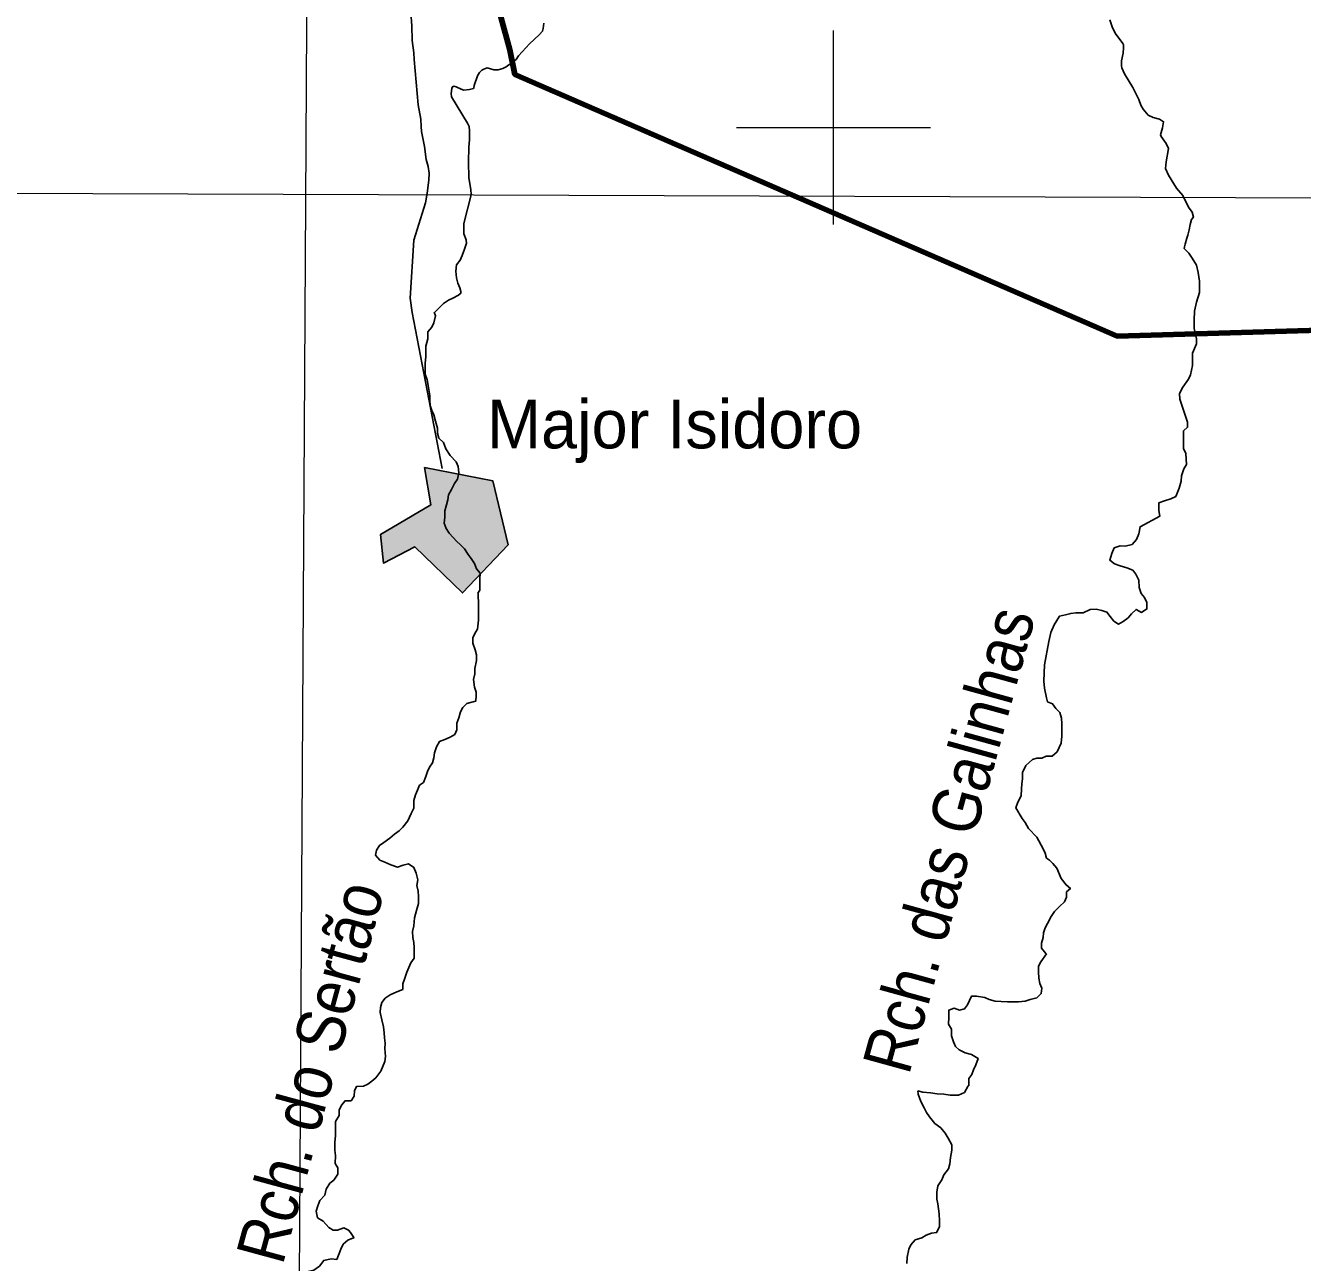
# Model space of a CAD drawing. Extents: x 553962 to 842807, y 8883888 to 9032388.
# Drawn here: x 716676 to 729831, y 8938306 to 8951050 of the extents above; entities that cross this region are included whole.
import ezdxf
from ezdxf.enums import TextEntityAlignment as Align

# ---------------------------------------------------------------- set-up
doc = ezdxf.new("R2010")
doc.units = 0
doc.header["$LTSCALE"] = 200
for name, color, linetype, lineweight in [('1', 7, 'Continuous', 13), ('12', 7, 'Continuous', 25), ('2', 7, 'Continuous', 13), ('21', 7, 'Continuous', 25), ('24', 7, 'Continuous', 25), ('9', 7, 'Continuous', 90)]:
    doc.layers.add(name, color=color, linetype=linetype, lineweight=lineweight)
doc.layers.add('41', color=7, linetype='Continuous')
doc.layers.add('49', color=7, linetype='Continuous')

msp = doc.modelspace()

# ---------------------------------------------------------------- hatches: boundary and pattern name
at = {"layer": '21'}
msp.add_hatch(color=256, dxfattribs=at).paths.add_polyline_path([(720787.1, 8946496.4), (720850.6, 8946110.2), (720334.5, 8945806.5), (720363, 8945511.1), (720684.9, 8945680.2), (721175.9, 8945203.6), (721647.6, 8945700.8), (721491.5, 8946358.8)])

# ---------------------------------------------------------------- linework, layer by layer
at = {"layer": '1'}
msp.add_line((565315.3, 8949866.8), (791497.7, 8949052.2), dxfattribs=at)
msp.add_lwpolyline([(719978.9, 9023574.5), (719561.6, 8949232.2), (719215.6, 8890710.6)], dxfattribs=at)
at = {"layer": '12'}
for points in [[(720644.9, 8951350), (720646.6, 8951317.5), (720645, 8951184.2), (720655.2, 8951046.6), (720660.7, 8950896.5), (720676.6, 8950767.3), (720679.5, 8950698.6), (720720, 8950234.3), (720748.8, 8950083.7), (720750.6, 8950010.8), (720756.6, 8949959.2), (720786.4, 8949804.4), (720801.7, 8949671.1), (720822.7, 8949598), (720833.3, 8949529.3), (720830.9, 8949456.4), (720814.3, 8949323), (720797.8, 8949224.2)], [(720797.8, 8949224.2), (720675.5, 8948838), (720637.7, 8948242.1), (720657.5, 8948094.3), (720969.8, 8946485.6)]]:
    msp.add_lwpolyline(points, dxfattribs=at)
at = {"layer": '2'}
for p, q in [((725000, 8949000), (725000, 8951000)), ((724000, 8950000), (726000, 8950000))]:
    msp.add_line(p, q, dxfattribs=at)
at = {"layer": '21'}
msp.add_lwpolyline([(720787.1, 8946496.4), (720850.6, 8946110.2), (720334.5, 8945806.5), (720363, 8945511.1), (720684.9, 8945680.2), (721175.9, 8945203.6), (721647.6, 8945700.8), (721491.5, 8946358.8)], close=True, dxfattribs=at)
at = {"layer": '24'}
for points in [[(722016.1, 8951074.9), (722008, 8951019.3), (722000.1, 8950992.6), (721969, 8950952.7), (721869.3, 8950860.9), (721753, 8950739.2), (721728.9, 8950700.5), (721627.2, 8950625.8), (721594.7, 8950607.3), (721543.8, 8950594), (721500.2, 8950594.2), (721433.2, 8950614.3), (721396.2, 8950601.1), (721377.1, 8950590.3), (721351, 8950564.9), (721332.8, 8950532.1), (721297.2, 8950432.1), (721294.4, 8950408.3), (721289.9, 8950402.2), (721248.6, 8950389.7), (721192.8, 8950385.5), (721162.4, 8950393.5), (721112.3, 8950419.6), (721087.2, 8950423.9), (721075.9, 8950419.2), (721066.9, 8950399.9), (721059.7, 8950351.2), (721065.8, 8950315.3), (721229.4, 8950044.8), (721245.2, 8950008.3), (721250.1, 8949966.3)], [(727845.7, 8951109.5), (727868.8, 8951037.2), (727900.2, 8950972.9), (727980.7, 8950863.7), (727986.6, 8950849.9), (727988.4, 8950820.9), (727984.7, 8950765.2), (727967.7, 8950684.6), (727966.2, 8950633.4), (727970.7, 8950612.8), (727995.9, 8950553.3), (728084, 8950413), (728146, 8950288.8), (728166.5, 8950228.6), (728190.4, 8950188.3), (728241.6, 8950126.4), (728291.3, 8950100.9), (728357.7, 8950086.8), (728400.8, 8950059.1), (728388.3, 8949995.5), (728368.3, 8949923.4), (728374.6, 8949907.3), (728428.1, 8949834.8), (728450.3, 8949782.8), (728425.1, 8949647.1), (728421, 8949575.3), (728450.8, 8949507.4), (728532.8, 8949374.5), (728598.3, 8949300.4), (728656.5, 8949177.3)], [(721250.1, 8949966.3), (721250.2, 8949871.2), (721250.2, 8949871.2), (721243.6, 8949796.7), (721237.8, 8949646.3), (721241.5, 8949480.6), (721262.5, 8949362.2), (721267.9, 8949307.1), (721191.4, 8949010.2)], [(728656.5, 8949177.3), (728694.1, 8949128.8), (728707.6, 8949076.1), (728689.3, 8949050.9), (728673.1, 8949000.2), (728664.5, 8948946.7), (728650.8, 8948890.9), (728640, 8948857.9), (728623.6, 8948797), (728615.5, 8948769.1), (728612.7, 8948751.6)], [(721191.4, 8949010.2), (721191, 8948954.2), (721190.6, 8948903.3), (721215.6, 8948842), (721218.6, 8948805.4)], [(721219.8, 8948809.2), (721199.7, 8948745.4), (721173.8, 8948679.3), (721153.2, 8948633.6), (721114.3, 8948584.8), (721107.6, 8948519.8), (721114.3, 8948450.3), (721131.2, 8948394.4), (721151.2, 8948348.5), (721164.9, 8948297.2)], [(728612.7, 8948751.6), (728660.2, 8948703.4), (728695.4, 8948652.3), (728740.7, 8948580.7), (728755.4, 8948504.2), (728770.1, 8948417.6), (728769.8, 8948366.6), (728769.3, 8948300.4), (728738.1, 8948198.8), (728717.1, 8948107.2), (728716.5, 8948015.6), (728715.9, 8947929), (728740.6, 8947821.9), (728740.2, 8947771), (728698.8, 8947674.5), (728698.3, 8947603.2), (728698, 8947547.2), (728677, 8947450.6), (728656.3, 8947404.9), (728599.8, 8947323.7), (728563.7, 8947257.7), (728568.4, 8947201.7), (728648.1, 8946961.9), (728647.8, 8946910.9), (728606.8, 8946875.6), (728606.5, 8946824.6), (728605.9, 8946743.2), (728605.6, 8946692.2), (728630.7, 8946641.2), (728635, 8946529.1), (728609.2, 8946483.4), (728583.3, 8946412.3), (728582.9, 8946356.3), (728562.1, 8946285.1), (728525.9, 8946198.8), (728474.8, 8946173.6), (728408.6, 8946153.6), (728352.5, 8946133.6), (728351.9, 8946052.1), (728361.7, 8945996.1), (728366, 8945992.5)], [(721162.8, 8948295.4), (721135.4, 8948272.2), (721079.2, 8948242), (721033.3, 8948221.9), (720982.2, 8948186.6), (720946.4, 8948151.1), (720887.8, 8948093.3)], [(720886.8, 8948096.7), (720898.2, 8948057.6), (720882.5, 8947986.4), (720861.8, 8947940.7), (720820.8, 8947895.1), (720820.3, 8947823.8), (720799.5, 8947747.6), (720798.7, 8947640.7), (720793.1, 8947569.4), (720792.8, 8947518.5), (720792.4, 8947457.4), (720812.3, 8947401.2), (720827, 8947319.7), (720841.7, 8947238.1), (720841.4, 8947187.2), (720846.1, 8947136.2), (720861, 8947085.2), (720881, 8947039.2), (720900.9, 8946972.9), (720920.8, 8946901.5), (720920.4, 8946850.6), (720935.3, 8946799.6), (720980.8, 8946753.5), (721005.7, 8946687.1), (721051.1, 8946620.6), (721111.6, 8946554.1), (721131.6, 8946508.1), (721141.3, 8946441.8), (721125.6, 8946375.7), (721094.8, 8946330.1), (721063.9, 8946269.2), (721033, 8946213.3), (721027.5, 8946162.4), (721011.9, 8946111.6), (720996.2, 8946050.6), (720995.8, 8945984.4), (720990.3, 8945923.3), (721010.2, 8945867.2), (721040.4, 8945821.2), (721080.8, 8945775.1), (721116.2, 8945739.2), (721156.6, 8945698.2), (721197, 8945657.3), (721237.2, 8945601), (721267.5, 8945560.1)], [(728361.7, 8945996.1), (728157.5, 8945885.3), (728146.8, 8945814.1), (728121, 8945753.1), (728074.9, 8945702.5), (728003.6, 8945687.6), (727952.7, 8945687.9), (727891.5, 8945667.9), (727865.7, 8945612.1), (727844.9, 8945540.9), (727895.5, 8945505), (727951.3, 8945484.2), (728022.4, 8945463.4), (728083.2, 8945437.6), (728113.5, 8945396.7), (728143.5, 8945335.4), (728148.1, 8945259), (728168, 8945197.7), (728203.3, 8945156.8), (728228.4, 8945105.7), (728228, 8945039.5), (728171.8, 8945004.2), (728116, 8945035.1), (728069.9, 8944989.6), (728034.1, 8944949), (727982.9, 8944908.6), (727937, 8944883.4), (727886.3, 8944914.3), (727851, 8944960.3), (727815.8, 8945006.4), (727765, 8945022), (727704.1, 8945037.6), (727643, 8945032.9), (727571.6, 8944997.7), (727495.3, 8944998.2), (727444.4, 8944993.4), (727388.3, 8944978.4), (727327.2, 8944963.6), (727273, 8944875.7), (727239.5, 8944797.4), (727239.5, 8944797.4), (727217.1, 8944704.3), (727172.4, 8944462.1)], [(721267.5, 8945560.1), (721302.7, 8945508.9), (721322.7, 8945452.8), (721358, 8945406.8), (721357.6, 8945345.6), (721357.2, 8945289.6), (721356.8, 8945233.6), (721336.6, 8945202.4)], [(721333.1, 8944831.8), (721314, 8944802.2), (721283.1, 8944746.3), (721282.7, 8944685.2), (721307.7, 8944618.9), (721322.6, 8944567.9), (721322.1, 8944506.8), (721306.3, 8944425.4), (721305.9, 8944369.4), (721290.3, 8944313.4), (721299.9, 8944231.9), (721319.9, 8944180.8), (721319.5, 8944129.9), (721309.9, 8944083.2)], [(727172.4, 8944462.1), (727164.9, 8944294.4), (727172.4, 8944223.6), (727194.7, 8944123), (727205.5, 8944081.4), (727256.2, 8944060.7), (727291.5, 8944014.6), (727331.9, 8943973.7), (727346.8, 8943912.4), (727351.5, 8943856.4), (727351.1, 8943800.4), (727350.6, 8943729.1), (727345, 8943657.8), (727324.3, 8943612.1), (727303.7, 8943566.4), (727252.5, 8943520.9), (727191.5, 8943521.3), (727145.6, 8943501.2), (727094.7, 8943501.5), (727048.8, 8943486.5), (726982.3, 8943425.8), (726946.2, 8943354.7), (726945.7, 8943288.5), (726940.3, 8943237.7), (726934.9, 8943186.8), (726934.4, 8943115.5), (726898.3, 8943049.5), (726877.6, 8942988.5), (726942.9, 8942881.2), (726973.2, 8942840.2), (727008.3, 8942778.9), (727094.2, 8942686.7), (727159.5, 8942569.2), (727179.5, 8942523.2), (727194.4, 8942472.2)], [(721311.4, 8944090.8), (721222.4, 8944064.3), (721181.5, 8944023.8), (721155.7, 8943978.2), (721140.1, 8943917.2), (721119.3, 8943861.3), (721118.9, 8943795.1), (721098.2, 8943744.3), (721052.2, 8943719.1), (720996.1, 8943694), (720940, 8943673.9), (720909.1, 8943618.1), (720888.3, 8943557.1), (720882.9, 8943506.2), (720867.3, 8943455.4), (720836.5, 8943409.8), (720815.8, 8943364.1), (720800.2, 8943313.2), (720774.3, 8943252.3), (720733.5, 8943222), (720712.8, 8943171.2), (720692.1, 8943125.5), (720676.4, 8943064.5), (720675.9, 8942988.1), (720650.1, 8942932.2), (720613.9, 8942856.1), (720562.6, 8942790.2), (720526.8, 8942754.7), (720475.7, 8942719.4), (720429.6, 8942678.9), (720368.3, 8942633.5), (720322.3, 8942603.2), (720291.4, 8942552.5), (720280.9, 8942501.6), (720326.3, 8942450.4), (720377, 8942429.8), (720437.9, 8942403.9), (720508.9, 8942378), (720565, 8942398), (720621, 8942413), (720676.7, 8942377), (720701.7, 8942315.7), (720716.5, 8942249.4), (720706, 8942188.4), (720720.8, 8942132.3), (720725.5, 8942076.2), (720725, 8942004.9), (720704.2, 8941933.8), (720683.3, 8941857.5), (720677.7, 8941776.1), (720662, 8941715.1), (720666.7, 8941653.9), (720676.5, 8941602.9), (720681.2, 8941552), (720680.8, 8941501.1), (720680.4, 8941440), (720644.5, 8941394.3), (720623.8, 8941343.6), (720603.2, 8941297.8), (720582.4, 8941236.9), (720561.6, 8941175.9), (720561.2, 8941119.9), (720500, 8941094.8), (720433.7, 8941064.6), (720382.6, 8941029.3), (720346.7, 8940983.7), (720331.1, 8940932.9), (720330.7, 8940881.9), (720345.5, 8940805.5), (720365.3, 8940734), (720370, 8940672.9), (720374.7, 8940621.9), (720379.4, 8940565.9), (720379, 8940509.9), (720383.5, 8940428.4), (720378.1, 8940377.5), (720336.7, 8940275.9), (720285.4, 8940210), (720244.5, 8940174.6), (720203.6, 8940144.3), (720157.6, 8940124.2), (720086.4, 8940119.6), (720065.7, 8940073.9), (720060.3, 8940017.9), (720029.4, 8939972.2), (719968.4, 8939972.6), (719932.5, 8939927), (719906.7, 8939876.2), (719906.3, 8939820.2), (719870.3, 8939759.3), (719869.9, 8939703.3), (719869.3, 8939611.7), (719863.7, 8939545.5), (719863.2, 8939464), (719867.9, 8939408), (719867.3, 8939326.5), (719892.4, 8939280.5), (719892, 8939214.3), (719850.8, 8939153.5), (719810, 8939123.2), (719773.9, 8939062.3)], [(727194.4, 8942472.2), (727224.8, 8942451.7), (727260.1, 8942415.8), (727300.5, 8942369.7), (727345.5, 8942262.5), (727395.9, 8942196), (727441.4, 8942160.1), (727443.2, 8942160.1)], [(727441.4, 8942160.1), (727400.5, 8942124.7), (727400.1, 8942068.7), (727379.5, 8942023), (727328.2, 8941972.3), (727277, 8941921.7), (727241.1, 8941871), (727205, 8941800), (727179.2, 8941754.3), (727163.6, 8941703.5), (727158.2, 8941652.6), (727142.6, 8941596.7), (727142.2, 8941545.7), (727187.6, 8941489.4), (727193.7, 8941485.1)], [(727194.1, 8941484.8), (727136.1, 8941403.2), (727110.4, 8941357.5), (727110, 8941301.5), (727114.6, 8941235.3), (727124.4, 8941179.2), (727144.4, 8941133.2), (727139, 8941077.2), (727092.9, 8941031.7), (727026.7, 8941016.8), (726975.7, 8940996.8), (726904.4, 8940992.1), (726853.6, 8940992.4), (726792.5, 8940992.8), (726726.4, 8940993.2), (726665.4, 8940998.7), (726604.5, 8941014.3), (726558.9, 8941035), (726472.5, 8941050.8), (726421.7, 8941051.1), (726380.3, 8940959.7), (726349.5, 8940919.1), (726298.6, 8940904.2), (726242.8, 8940924.9), (726186.7, 8940904.8), (726186.2, 8940833.6), (726185.7, 8940762.3), (726215.9, 8940711.2), (726215.4, 8940639.9), (726235.3, 8940578.6), (726255.3, 8940532.7), (726295.8, 8940496.8), (726356.6, 8940465.9), (726422.6, 8940450.2), (726488.4, 8940409), (726467.6, 8940343), (726441.8, 8940292.2), (726426.2, 8940241.4), (726395.4, 8940200.8), (726394.9, 8940125.5)], [(725866.7, 8940074.6), (725866.7, 8940073.8), (725872.8, 8940040.7), (725897.7, 8939964.2), (725932.8, 8939897.8), (725957.9, 8939851.8), (725988.1, 8939805.8), (726043.6, 8939739.2), (726104.3, 8939693), (726149.7, 8939636.7), (726179.9, 8939585.6), (726220.1, 8939519.2), (726219.7, 8939463.2), (726203.9, 8939386.9), (726198.4, 8939320.7), (726182.8, 8939269.9), (726136.6, 8939209.1), (726115.9, 8939158.2), (726074.8, 8939097.4), (726064.2, 8939031.3), (726063.7, 8938960), (726073.5, 8938909), (726088, 8938807.1), (726092.6, 8938730.6), (726092.2, 8938674.6), (726061.2, 8938613.7), (726010.4, 8938608.9), (725954.3, 8938588.9), (725908.3, 8938558.6), (725842, 8938538.7), (725795.9, 8938488)], [(726388.5, 8940126.2), (726348.7, 8940058.5), (726287.4, 8940028.3), (726201, 8940028.9), (726134.9, 8940039.4), (726068.8, 8940044.9), (725997.7, 8940055.6), (725921.5, 8940061.1), (725866.7, 8940073.8), (725866.7, 8940073.8)], [(719773.9, 8939062.3), (719758.2, 8939001.2), (719707, 8938945.6), (719686.3, 8938889.7), (719670.6, 8938833.7), (719685.4, 8938767.4), (719741.1, 8938731.5), (719801.7, 8938664.9), (719844, 8938640.7), (719890.2, 8938638.6), (719890.2, 8938638.6)], [(719890.2, 8938638.6), (719953.8, 8938664.2), (720004.3, 8938640.4), (720024.2, 8938614.6), (720058.9, 8938563), (720061.4, 8938559.7)], [(720060.8, 8938559.8), (720055.8, 8938559.8), (719994.6, 8938534.7), (719948.5, 8938494.2), (719922.7, 8938443.5), (719881.3, 8938336.8), (719825.4, 8938342.2), (719749, 8938327.4), (719702.8, 8938266.6), (719646.6, 8938226.2), (719575.3, 8938211.3), (719495.9, 8938211.8)], [(725795.9, 8938488), (725775.3, 8938442.3), (725759.4, 8938360.9), (725753.9, 8938294.8)]]:
    msp.add_lwpolyline(points, dxfattribs=at)
msp.add_spline([(721338.8, 8945205.7), (721343, 8945051.6), (721343, 8944957), (721332, 8944830.1)], degree=3, dxfattribs=at)
at = {"layer": '9'}
msp.add_lwpolyline([(717295.3, 8959630.3), (717636.9, 8956393.6), (717537.2, 8955887), (718376.1, 8955487), (718808.6, 8955185.8), (719472.1, 8954177.6), (719984.6, 8952814.2), (721077.3, 8952390.4), (721486.8, 8951456.6), (721666.8, 8950799.8), (721718.4, 8950547.1), (727920.4, 8947850.3), (733274.5, 8948007.9), (737635.8, 8948628.8)], dxfattribs=at)

# ---------------------------------------------------------------- texts
at = {"layer": '41'}
msp.add_text('Major Isidoro', height=500, dxfattribs=at).set_placement((721429.9, 8946693.7))
at = {"layer": '49', "width": 0.9}
for s, rotation, p in [('Rch. das Galinhas', 74.592, (726429.3, 8942595.9)), ('Rch. do Sertão', 74.808, (719849.9, 8940205))]:
    msp.add_text(s, height=500, rotation=rotation, dxfattribs=at).set_placement(p, align=Align.CENTER)

doc.saveas('drawing.dxf')
